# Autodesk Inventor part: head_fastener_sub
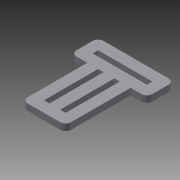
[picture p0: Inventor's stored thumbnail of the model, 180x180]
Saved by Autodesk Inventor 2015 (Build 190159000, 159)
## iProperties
Created: 2015-06
Part Number: head_fastener_sub
Material: Generic
Document SubType Name: Modeling
Designer: sungeun
Density: 1 g/cm^3
Appearance: Default
Author: sungeun
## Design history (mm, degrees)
sketch "Sketch1" dims "d8" = 10
  geometry: L1 (-10, 25)-(-5, 25); L2 (-5, 25)-(-5, -25); L3 (-5, -25)-(-10, -25); L4 (-10, -25)-(-10, 25); L5 (5, 25)-(10, 25); L6 (5, -25)-(5, 25); L7 (10, 25)-(10, -25); L8 (10, -25)-(5, -25); L9 (-25, 40)-(25, 40); L10 (25, 40)-(25, 35); L11 (25, 35)-(-25, 35); L12 (-25, 35)-(-25, 40); L13 (-35, 50)-(35, 50); L14 (35, 50)-(35, 25); L15 (35, 25)-(20, 25); L16 (20, 25)-(20, -35); L17 (20, -35)-(-20, -35); L18 (-20, -35)-(-20, 25); L19 (-20, 25)-(-35, 25); L20 (-35, 25)-(-35, 50); 5 further points
  constraints: 40 end point, 8 perpendicular, 4 horizontal, 4 parallel, 2 midpoint, 1 coincident, 1 collinear, 1 horizontal alignment, 1 vertical, 1 vertical alignment, 8 other
  dimensions: "d0" = 5 distance of L2.end L3.end; "d1" = 50 distance of L3.end L1.start; "d2" = 5 distance from line of L2 point (0, 0); "d5" = 15 distance of L1.start L5.start; "d10" = 5 distance of L9.end L10.end; "d11" = 50 distance of L9.start L9.end; "d12" = 10 distance between parallel lines of L5 L11; "d13" = 10 distance between parallel lines of L16 L7; "d14" = 10 distance between parallel lines of L18 L4; "d15" = 10 distance between parallel lines of L8 L17; "d16" = 10 distance between parallel lines of L13 L9; "d17" = 10 distance between parallel lines of L14 L10; "d18" = 10 distance between parallel lines of L15 L11; "d19" = 10 distance between parallel lines of L11 L19; "d20" = 10 distance between parallel lines of L12 L20
extrude "Extrusion1" new body sketch "Sketch1" distance "d21" = 6; taper "d22" = 0 deg
fillet "Fillet1" dims "d23" = 5
body "Solid1"
